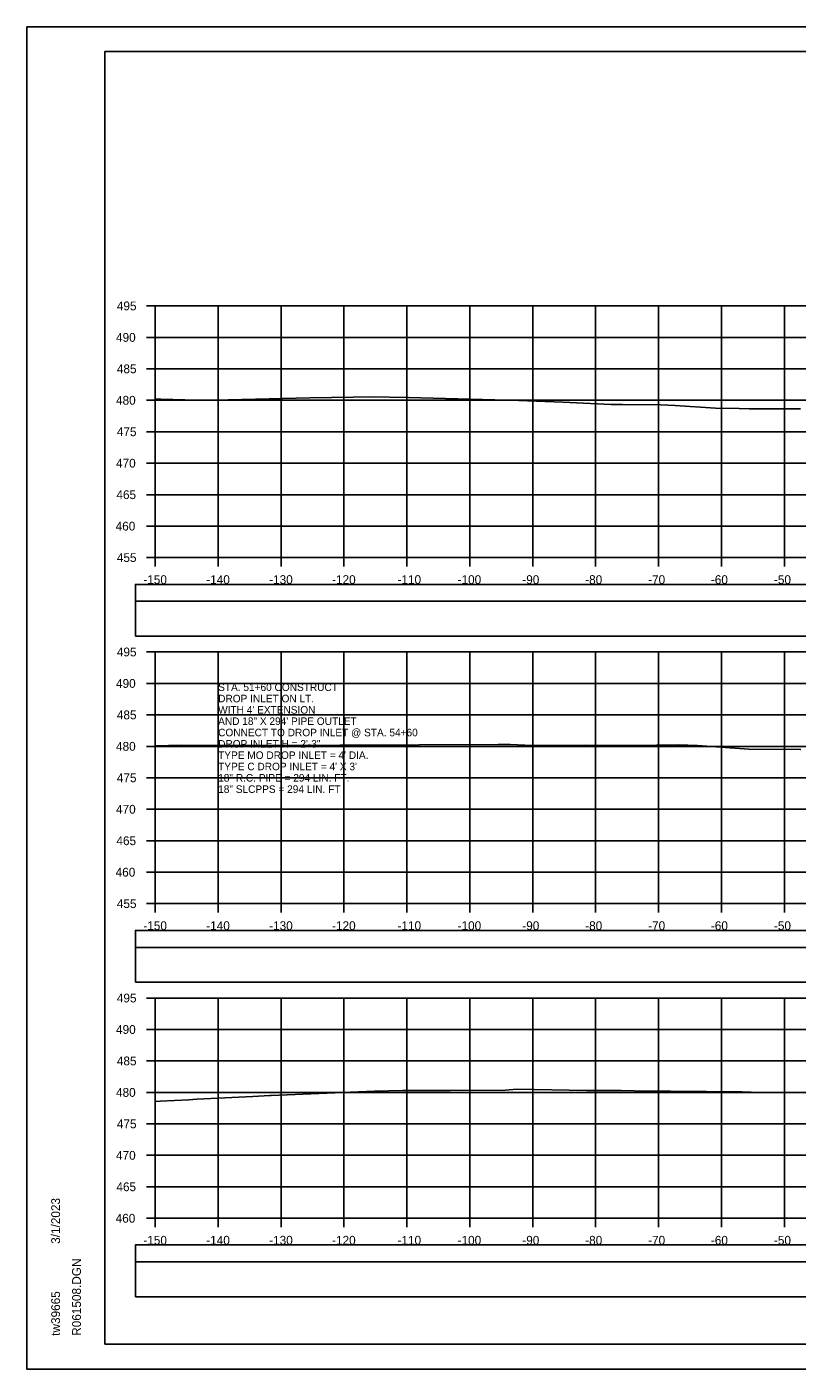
# Model space of a CAD drawing. Extents: x 1371057 to 1372761, y 380005 to 390517.
# Drawn here: x 1371390.5 to 1371512.9, y 383205.1 to 383418.5 of the extents above; entities that cross this region are included whole.
import ezdxf

# ---------------------------------------------------------------- set-up
doc = ezdxf.new("R2010")
doc.units = 0
for name, color, linetype in [('R_Axis', 7, 'Continuous'), ('R_Axis Annot', 7, 'Continuous'), ('R_Border', 7, 'Continuous'), ('R_Detour', 7, 'Continuous'), ('R_Dimension', 7, 'Continuous'), ('R_Exist Surface', 7, 'Continuous'), ('R_Grid', 7, 'Continuous'), ('R_No Plot', 7, 'Continuous'), ('R_Water Annot', 7, 'Continuous')]:
    doc.layers.add(name, color=color, linetype=linetype)

msp = doc.modelspace()

# ---------------------------------------------------------------- linework, layer by layer
at = {"layer": 'R_Axis'}
for p, q in [((1371409.47, 383374.13), (1371410.87, 383374.13)), ((1371410.87, 383334.13), (1371410.87, 383374.13)), ((1371409.47, 383369.13), (1371410.87, 383369.13)), ((1371409.47, 383364.13), (1371410.87, 383364.13)), ((1371409.47, 383359.13), (1371410.87, 383359.13)), ((1371409.47, 383354.13), (1371410.87, 383354.13)), ((1371409.47, 383349.13), (1371410.87, 383349.13)), ((1371409.47, 383344.13), (1371410.87, 383344.13)), ((1371409.47, 383339.13), (1371410.87, 383339.13)), ((1371409.47, 383334.13), (1371410.87, 383334.13)), ((1371410.87, 383334.13), (1371710.87, 383334.13)), ((1371410.87, 383332.73), (1371410.87, 383334.13)), ((1371420.87, 383332.73), (1371420.87, 383334.13)), ((1371430.87, 383332.73), (1371430.87, 383334.13)), ((1371440.87, 383332.73), (1371440.87, 383334.13)), ((1371450.87, 383332.73), (1371450.87, 383334.13)), ((1371460.87, 383332.73), (1371460.87, 383334.13)), ((1371470.87, 383332.73), (1371470.87, 383334.13)), ((1371480.87, 383332.73), (1371480.87, 383334.13)), ((1371490.87, 383332.73), (1371490.87, 383334.13)), ((1371500.87, 383332.73), (1371500.87, 383334.13)), ((1371510.87, 383332.73), (1371510.87, 383334.13)), ((1371409.47, 383319.13), (1371410.87, 383319.13)), ((1371410.87, 383279.13), (1371410.87, 383319.13)), ((1371409.47, 383314.13), (1371410.87, 383314.13)), ((1371409.47, 383309.13), (1371410.87, 383309.13)), ((1371409.47, 383304.13), (1371410.87, 383304.13)), ((1371409.47, 383299.13), (1371410.87, 383299.13)), ((1371409.47, 383294.13), (1371410.87, 383294.13)), ((1371409.47, 383289.13), (1371410.87, 383289.13)), ((1371409.47, 383284.13), (1371410.87, 383284.13)), ((1371409.47, 383279.13), (1371410.87, 383279.13)), ((1371410.87, 383279.13), (1371710.87, 383279.13)), ((1371410.87, 383277.73), (1371410.87, 383279.13)), ((1371420.87, 383277.73), (1371420.87, 383279.13)), ((1371430.87, 383277.73), (1371430.87, 383279.13)), ((1371440.87, 383277.73), (1371440.87, 383279.13)), ((1371450.87, 383277.73), (1371450.87, 383279.13)), ((1371460.87, 383277.73), (1371460.87, 383279.13)), ((1371470.87, 383277.73), (1371470.87, 383279.13)), ((1371480.87, 383277.73), (1371480.87, 383279.13)), ((1371490.87, 383277.73), (1371490.87, 383279.13)), ((1371500.87, 383277.73), (1371500.87, 383279.13)), ((1371510.87, 383277.73), (1371510.87, 383279.13)), ((1371409.47, 383264.13), (1371410.87, 383264.13)), ((1371410.87, 383229.13), (1371410.87, 383264.13)), ((1371409.47, 383259.13), (1371410.87, 383259.13)), ((1371409.47, 383254.13), (1371410.87, 383254.13)), ((1371409.47, 383249.13), (1371410.87, 383249.13)), ((1371409.47, 383244.13), (1371410.87, 383244.13)), ((1371409.47, 383239.13), (1371410.87, 383239.13)), ((1371409.47, 383234.13), (1371410.87, 383234.13)), ((1371409.47, 383229.13), (1371410.87, 383229.13)), ((1371410.87, 383229.13), (1371710.87, 383229.13)), ((1371410.87, 383227.73), (1371410.87, 383229.13)), ((1371420.87, 383227.73), (1371420.87, 383229.13)), ((1371430.87, 383227.73), (1371430.87, 383229.13)), ((1371440.87, 383227.73), (1371440.87, 383229.13)), ((1371450.87, 383227.73), (1371450.87, 383229.13)), ((1371460.87, 383227.73), (1371460.87, 383229.13)), ((1371470.87, 383227.73), (1371470.87, 383229.13)), ((1371480.87, 383227.73), (1371480.87, 383229.13)), ((1371490.87, 383227.73), (1371490.87, 383229.13)), ((1371500.87, 383227.73), (1371500.87, 383229.13)), ((1371510.87, 383227.73), (1371510.87, 383229.13))]:
    msp.add_line(p, q, dxfattribs=at)
at = {"layer": 'R_Border'}
for p, q in [((1371402.87, 383414.59), (1371719.05, 383414.59)), ((1371402.87, 383209.13), (1371402.87, 383414.59)), ((1371402.87, 383209.13), (1371402.87, 383209.13)), ((1371719.05, 383209.13), (1371402.87, 383209.13))]:
    msp.add_line(p, q, dxfattribs=at)
at = {"layer": 'R_Detour'}
for points in [[(1371407.72, 383327.18), (1371714.03, 383327.18), (1371714.03, 383329.88), (1371407.72, 383329.88)], [(1371407.72, 383272.18), (1371714.03, 383272.18), (1371714.03, 383274.88), (1371407.72, 383274.88)], [(1371407.72, 383222.18), (1371714.03, 383222.18), (1371714.03, 383224.88), (1371407.72, 383224.88)]]:
    msp.add_lwpolyline(points, close=True, dxfattribs=at)
at = {"layer": 'R_Dimension'}
for points in [[(1371407.72, 383321.65), (1371714.03, 383321.65), (1371714.03, 383327.18), (1371407.72, 383327.18)], [(1371407.72, 383266.65), (1371714.03, 383266.65), (1371714.03, 383272.18), (1371407.72, 383272.18)], [(1371407.72, 383216.65), (1371714.03, 383216.65), (1371714.03, 383222.18), (1371407.72, 383222.18)]]:
    msp.add_lwpolyline(points, close=True, dxfattribs=at)
at = {"layer": 'R_Exist Surface'}
for points in [[(1371410.87, 383359.33), (1371411.75, 383359.32), (1371417.49, 383359.15), (1371419.94, 383359.16), (1371422.45, 383359.19), (1371435.45, 383359.51), (1371442.35, 383359.65), (1371445.03, 383359.69), (1371451.13, 383359.6), (1371464.86, 383359.23), (1371468.65, 383359.11), (1371475.66, 383358.84), (1371483.34, 383358.47), (1371485.14, 383358.44), (1371491.19, 383358.4), (1371493.53, 383358.3), (1371499.94, 383357.86), (1371503.69, 383357.85), (1371505.26, 383357.79), (1371513.45, 383357.78)], [(1371410.87, 383304.22), (1371415.08, 383304.3), (1371427.66, 383304.28), (1371465.39, 383304.45), (1371467.27, 383304.43), (1371469.63, 383304.33), (1371471.06, 383304.28), (1371479.28, 383304.3), (1371487, 383304.26), (1371494.01, 383304.36), (1371495.52, 383304.32), (1371497.03, 383304.26), (1371505.2, 383303.67), (1371513.47, 383303.61)], [(1371410.87, 383247.69), (1371411.67, 383247.74), (1371416.21, 383247.93), (1371417.5, 383248.03), (1371426.37, 383248.49), (1371429.1, 383248.64), (1371429.29, 383248.65), (1371445.73, 383249.34), (1371450.17, 383249.42), (1371451.85, 383249.46), (1371457.73, 383249.44), (1371466.52, 383249.47), (1371468.33, 383249.62), (1371479.41, 383249.42), (1371484.91, 383249.41), (1371487.04, 383249.39), (1371504.15, 383249.2), (1371505.59, 383249.18), (1371514.27, 383249.06)]]:
    msp.add_lwpolyline(points, dxfattribs=at)
at = {"layer": 'R_Grid'}
for p, q in [((1371410.87, 383374.13), (1371710.87, 383374.13)), ((1371410.87, 383334.13), (1371410.87, 383374.13)), ((1371420.87, 383334.13), (1371420.87, 383374.13)), ((1371430.87, 383334.13), (1371430.87, 383374.13)), ((1371440.87, 383334.13), (1371440.87, 383374.13)), ((1371450.87, 383334.13), (1371450.87, 383374.13)), ((1371460.87, 383334.13), (1371460.87, 383374.13)), ((1371470.87, 383334.13), (1371470.87, 383374.13)), ((1371480.87, 383334.13), (1371480.87, 383374.13)), ((1371490.87, 383334.13), (1371490.87, 383374.13)), ((1371500.87, 383334.13), (1371500.87, 383374.13)), ((1371510.87, 383334.13), (1371510.87, 383374.13)), ((1371410.87, 383369.13), (1371710.87, 383369.13)), ((1371410.87, 383364.13), (1371710.87, 383364.13)), ((1371410.87, 383359.13), (1371710.87, 383359.13)), ((1371410.87, 383354.13), (1371710.87, 383354.13)), ((1371410.87, 383349.13), (1371710.87, 383349.13)), ((1371410.87, 383344.13), (1371710.87, 383344.13)), ((1371410.87, 383339.13), (1371710.87, 383339.13)), ((1371410.87, 383334.13), (1371710.87, 383334.13)), ((1371410.87, 383319.13), (1371710.87, 383319.13)), ((1371410.87, 383279.13), (1371410.87, 383319.13)), ((1371420.87, 383279.13), (1371420.87, 383319.13)), ((1371430.87, 383279.13), (1371430.87, 383319.13)), ((1371440.87, 383279.13), (1371440.87, 383319.13)), ((1371450.87, 383279.13), (1371450.87, 383319.13)), ((1371460.87, 383279.13), (1371460.87, 383319.13)), ((1371470.87, 383279.13), (1371470.87, 383319.13)), ((1371480.87, 383279.13), (1371480.87, 383319.13)), ((1371490.87, 383279.13), (1371490.87, 383319.13)), ((1371500.87, 383279.13), (1371500.87, 383319.13)), ((1371510.87, 383279.13), (1371510.87, 383319.13)), ((1371410.87, 383314.13), (1371710.87, 383314.13)), ((1371410.87, 383309.13), (1371710.87, 383309.13)), ((1371410.87, 383304.13), (1371710.87, 383304.13)), ((1371410.87, 383299.13), (1371710.87, 383299.13)), ((1371410.87, 383294.13), (1371710.87, 383294.13)), ((1371410.87, 383289.13), (1371710.87, 383289.13)), ((1371410.87, 383284.13), (1371710.87, 383284.13)), ((1371410.87, 383279.13), (1371710.87, 383279.13)), ((1371410.87, 383264.13), (1371710.87, 383264.13)), ((1371410.87, 383229.13), (1371410.87, 383264.13)), ((1371420.87, 383229.13), (1371420.87, 383264.13)), ((1371430.87, 383229.13), (1371430.87, 383264.13)), ((1371440.87, 383229.13), (1371440.87, 383264.13)), ((1371450.87, 383229.13), (1371450.87, 383264.13)), ((1371460.87, 383229.13), (1371460.87, 383264.13)), ((1371470.87, 383229.13), (1371470.87, 383264.13)), ((1371480.87, 383229.13), (1371480.87, 383264.13)), ((1371490.87, 383229.13), (1371490.87, 383264.13)), ((1371500.87, 383229.13), (1371500.87, 383264.13)), ((1371510.87, 383229.13), (1371510.87, 383264.13)), ((1371410.87, 383259.13), (1371710.87, 383259.13)), ((1371410.87, 383254.13), (1371710.87, 383254.13)), ((1371410.87, 383249.13), (1371710.87, 383249.13)), ((1371410.87, 383244.13), (1371710.87, 383244.13)), ((1371410.87, 383239.13), (1371710.87, 383239.13)), ((1371410.87, 383234.13), (1371710.87, 383234.13)), ((1371410.87, 383229.13), (1371710.87, 383229.13))]:
    msp.add_line(p, q, dxfattribs=at)
at = {"layer": 'R_No Plot'}
for p, q in [((1371390.47, 383418.48), (1371723.8, 383418.48)), ((1371390.47, 383205.15), (1371723.8, 383205.15))]:
    msp.add_line(p, q, dxfattribs=at)
for points in [[(1371390.46, 383418.48), (1371723.8, 383418.48), (1371723.8, 383205.15), (1371390.46, 383205.15)], [(1371636.79, 383414.59), (1371656.41, 383414.59), (1371656.41, 383404.71), (1371672.52, 383404.71), (1371695.72, 383404.71), (1371695.84, 383376.55), (1371719.05, 383376.55), (1371719.05, 383209.13), (1371402.87, 383209.13), (1371402.87, 383414.59)]]:
    msp.add_lwpolyline(points, close=True, dxfattribs=at)

# ---------------------------------------------------------------- texts
at = {"layer": 'R_Axis Annot'}
for s, p in [('495', (1371404.77, 383373.43)), ('490', (1371404.64, 383368.43)), ('485', (1371404.77, 383363.43)), ('480', (1371404.64, 383358.43)), ('475', (1371404.77, 383353.43)), ('470', (1371404.64, 383348.43)), ('465', (1371404.7, 383343.43)), ('460', (1371404.58, 383338.43)), ('455', (1371404.77, 383333.43)), ('-150', (1371408.98, 383329.93)), ('-140', (1371418.98, 383329.93)), ('-130', (1371428.98, 383329.93)), ('-120', (1371438.98, 383329.93)), ('-110', (1371449.38, 383329.93)), ('-100', (1371458.93, 383329.93)), ('-90', (1371469.21, 383329.93)), ('-80', (1371479.21, 383329.93)), ('-70', (1371489.21, 383329.93)), ('-60', (1371499.18, 383329.93)), ('-50', (1371509.21, 383329.93)), ('495', (1371404.77, 383318.43)), ('490', (1371404.64, 383313.43)), ('485', (1371404.77, 383308.43)), ('480', (1371404.64, 383303.43)), ('475', (1371404.77, 383298.43)), ('470', (1371404.64, 383293.43)), ('465', (1371404.7, 383288.43)), ('460', (1371404.58, 383283.43)), ('455', (1371404.77, 383278.43)), ('-150', (1371408.98, 383274.93)), ('-140', (1371418.98, 383274.93)), ('-130', (1371428.98, 383274.93)), ('-120', (1371438.98, 383274.93)), ('-110', (1371449.38, 383274.93)), ('-100', (1371458.93, 383274.93)), ('-90', (1371469.21, 383274.93)), ('-80', (1371479.21, 383274.93)), ('-70', (1371489.21, 383274.93)), ('-60', (1371499.18, 383274.93)), ('-50', (1371509.21, 383274.93)), ('495', (1371404.77, 383263.43)), ('490', (1371404.64, 383258.43)), ('485', (1371404.77, 383253.43)), ('480', (1371404.64, 383248.43)), ('475', (1371404.77, 383243.43)), ('470', (1371404.64, 383238.43)), ('465', (1371404.7, 383233.43)), ('460', (1371404.58, 383228.43)), ('-150', (1371408.98, 383224.93)), ('-140', (1371418.98, 383224.93)), ('-130', (1371428.98, 383224.93)), ('-120', (1371438.98, 383224.93)), ('-110', (1371449.38, 383224.93)), ('-100', (1371458.93, 383224.93)), ('-90', (1371469.21, 383224.93)), ('-80', (1371479.21, 383224.93)), ('-70', (1371489.21, 383224.93)), ('-60', (1371499.18, 383224.93)), ('-50', (1371509.21, 383224.93))]:
    msp.add_text(s, height=1.4, dxfattribs=at).set_placement(p)
at = {"layer": 'R_Border'}
for s, p in [('3/1/2023', (1371395.74, 383225.06)), ('R061508.DGN', (1371399.06, 383210.45)), ('tw39665', (1371395.74, 383210.45))]:
    msp.add_text(s, height=1.4, rotation=90, dxfattribs=at).set_placement(p)
at = {"layer": 'R_Water Annot'}
for s, p in [('STA. 51+60 CONSTRUCT', (1371420.87, 383312.93)), ('DROP INLET ON LT.', (1371420.87, 383311.13)), ("WITH 4' EXTENSION", (1371420.87, 383309.33)), ('AND 18" X 294\' PIPE OUTLET', (1371420.87, 383307.53)), ('CONNECT TO DROP INLET @ STA. 54+60', (1371420.87, 383305.73)), ('DROP INLET H = 2\'-3"', (1371420.87, 383303.93)), ("TYPE MO DROP INLET = 4' DIA.", (1371420.87, 383302.13)), ("TYPE C DROP INLET = 4' X 3'", (1371420.87, 383300.33)), ('18" R.C. PIPE = 294 LIN. FT.', (1371420.87, 383298.53)), ('18" SLCPPS = 294 LIN. FT', (1371420.87, 383296.73))]:
    msp.add_text(s, height=1.2, dxfattribs=at).set_placement(p)

doc.saveas('drawing.dxf')
